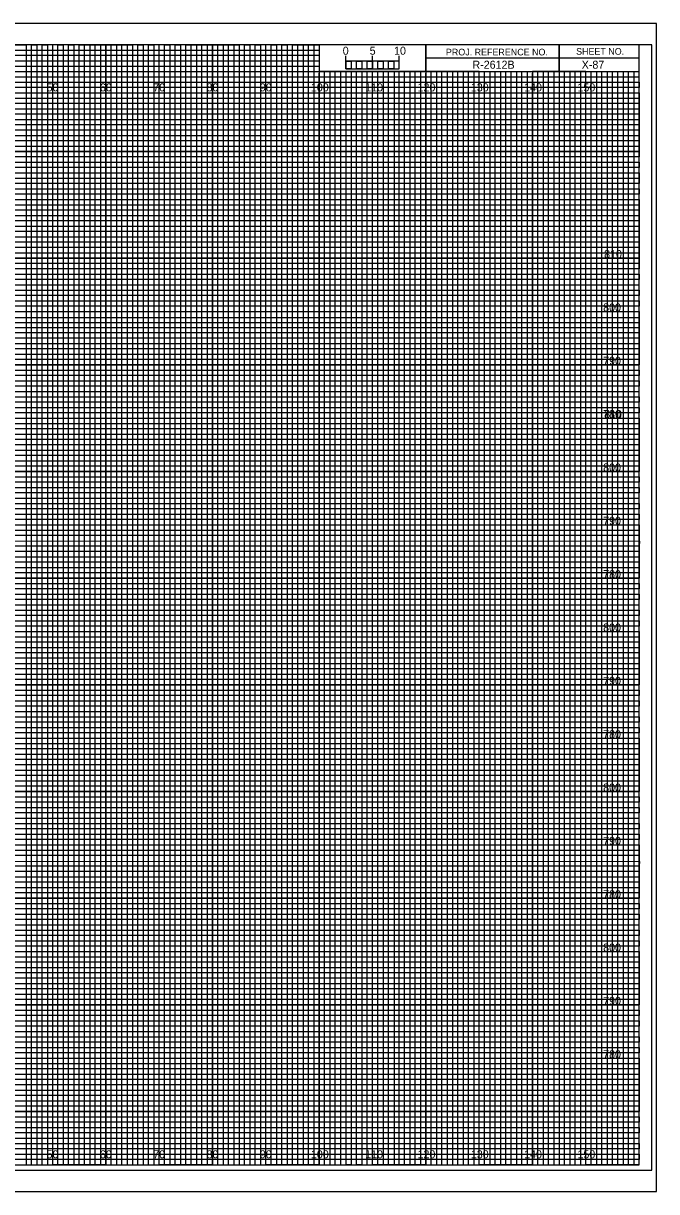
# Model space of a CAD drawing. Extents: x -13 to 323, y -5 to 214.
# Drawn here: x 204.5 to 323.3, y -5 to 214 of the extents above; entities that cross this region are included whole.
import ezdxf

# ---------------------------------------------------------------- set-up
doc = ezdxf.new("R2010")
doc.units = 0
for name, color, linetype in [('Prop XS Bar Scale Labels', 7, 'Continuous'), ('Prop XS Elevation Labels', 7, 'Continuous'), ('Prop XS Offset Labels', 7, 'Continuous'), ('Prop XS Project Number', 7, 'Continuous'), ('Prop XS Sheet Number', 7, 'Continuous'), ('Sheet Cross Section CELL', 7, 'Continuous'), ('Sheet Cross Section Grid Major CELL', 7, 'Continuous'), ('Sheet Cross Section Grid Middle CELL', 7, 'Continuous'), ('Sheet Cross Section Grid Minor 1 CELL', 7, 'Continuous'), ('Sheet Cross Section Grid Minor 2 CELL', 7, 'Continuous'), ('Sheet Cross Section Scale CELL', 7, 'Continuous'), ('Sheet Cutting Line CELL', 7, 'Continuous'), ('Sheet DOT Grid CELL', 7, 'Continuous'), ('Sheet Plot Border Inside CELL', 7, 'Continuous'), ('Sheet Plot Border Outside CELL', 7, 'Continuous')]:
    doc.layers.add(name, color=color, linetype=linetype)

msp = doc.modelspace()

# ---------------------------------------------------------------- linework, layer by layer
at = {"layer": 'Sheet Cross Section CELL'}
for p, q in [((305, 210), (305, 205)), ((305, 205), (305, 210)), ((280, 207.5), (280, 205)), ((320, 207.49), (280, 207.49)), ((280, 205), (320, 205))]:
    msp.add_line(p, q, dxfattribs=at)
for points in [[(320, 210), (0, 210), (0, 0), (320, 0)], [(280, 210), (260, 210), (260, 205.03), (280, 205.03)], [(320, 210), (280, 210), (280, 205), (320, 205)]]:
    msp.add_lwpolyline(points, close=True, dxfattribs=at)
at = {"layer": 'Sheet Cross Section Grid Major CELL'}
for p, q in [((210, 210), (200, 210)), ((210, 0), (210, 210)), ((230, 210), (220, 210)), ((220, 210), (220, 0)), ((230, 0), (230, 210)), ((250, 210), (240, 210)), ((240, 210), (240, 0)), ((250, 0), (250, 210)), ((260, 210), (260, 0)), ((270, 0), (270, 205)), ((290, 205), (280, 205)), ((280, 205), (280, 0)), ((290, 0), (290, 205)), ((310, 205), (300, 205)), ((300, 205), (300, 0)), ((310, 0), (310, 205)), ((220, 0), (210, 0)), ((240, 0), (230, 0)), ((260, 0), (250, 0)), ((280, 0), (270, 0)), ((300, 0), (290, 0)), ((320, 0), (310, 0)), ((320, 0), (320, 0))]:
    msp.add_line(p, q, dxfattribs=at)
for points in [[(0, 200), (320, 200), (320, 190), (0, 190)], [(0, 180), (320, 180), (320, 170), (0, 170)], [(0, 160), (320, 160), (320, 150), (0, 150)], [(0, 140), (320, 140), (320, 130), (0, 130)], [(0, 120), (320, 120), (320, 110), (0, 110)], [(0, 100), (320, 100), (320, 90), (0, 90)], [(0, 80), (320, 80), (320, 70), (0, 70)], [(0, 60), (320, 60), (320, 50), (0, 50)], [(0, 40), (320, 40), (320, 30), (0, 30)], [(0, 20), (320, 20), (320, 10), (0, 10)]]:
    msp.add_lwpolyline(points, dxfattribs=at)
at = {"layer": 'Sheet Cross Section Grid Middle CELL'}
for points in [[(195, 210), (205, 210), (205, 0), (215, 0), (215, 210), (225, 210), (225, 0), (235, 0), (235, 210), (245, 210), (245, 0), (255, 0), (255, 210), (259.93, 210), (260, 210), (260, 205), (264.99, 205), (264.99, 0), (275, 0), (275, 205), (285, 205), (285, 0), (295, 0), (295, 205), (305, 205), (305, 0), (315, 0), (315, 205)], [(0, 205), (275, 205)], [(0, 185), (320, 185), (320, 195), (0, 195)], [(0, 165), (320, 165), (320, 175), (0, 175)], [(0, 145), (320, 145), (320, 155), (0, 155)], [(0, 125), (320, 125), (320, 135), (0, 135)], [(0, 105), (320, 105), (320, 115), (0, 115)], [(0, 85), (320, 85), (320, 95), (0, 95)], [(0, 65), (320, 65), (320, 75), (0, 75)], [(0, 45), (320, 45), (320, 55), (0, 55)], [(0, 25), (320, 25), (320, 35), (0, 35)], [(0, 5), (320, 5), (320, 15), (0, 15)]]:
    msp.add_lwpolyline(points, dxfattribs=at)
at = {"layer": 'Sheet Cross Section Grid Minor 1 CELL'}
for p, q in [((0, 209), (260, 209)), ((260, 209), (260, 207.98)), ((260, 207.98), (0, 207.98)), ((0, 207), (260, 207)), ((260, 205.89), (0, 205.89)), ((260, 207), (260, 205.89)), ((0, 204), (320, 204))]:
    msp.add_line(p, q, dxfattribs=at)
for points in [[(0, 203), (270, 203), (320, 203), (320, 202), (0, 202)], [(0, 201), (320, 201), (320, 199), (0, 199)], [(0, 198), (320, 198), (320, 197), (0, 196.98)], [(0, 196), (320, 196), (320, 194), (0, 194)], [(0, 193), (320, 193), (320, 192), (0, 192)], [(0, 191), (320, 191), (320, 189), (0, 189)], [(0, 188), (320, 188), (320, 187), (0, 187)], [(0, 186), (320, 186), (320, 184), (0, 184)], [(0, 183), (320, 183), (320, 182), (0, 182)], [(0, 181), (320, 181), (320, 179), (0, 179)], [(0, 178), (320, 178), (320, 177), (0, 177)], [(0, 176), (320, 176), (320, 173.95), (320, 173), (320, 172), (0, 172)], [(0, 174), (320, 174), (320, 173), (0, 173)], [(0, 171), (320, 171), (320, 169), (0, 169.03)], [(0, 169.03), (320, 169), (320, 168), (0, 168)], [(0, 167), (320, 167), (320, 166), (0, 166)], [(0, 164), (320, 164), (320, 163), (0, 163)], [(0, 162), (320, 162), (320, 161), (0, 161)], [(-0.07, 158.89), (320, 158.89), (320, 157.88), (-0.07, 157.88)], [(0, 157), (320, 157), (320, 156), (0, 156)], [(0, 154), (320, 154), (320, 153), (0, 153)], [(0, 152), (320, 152), (320, 151), (0, 151)], [(0, 149), (320, 149), (320, 148), (0, 148)], [(0, 147), (320, 147), (320, 146), (0, 146)], [(0, 144), (320, 144), (320, 143), (0, 143)], [(0, 142), (320, 142), (320, 141), (0, 141)], [(0, 139), (320, 139), (319.99, 137.98), (0, 138)], [(0, 137), (320, 137), (320, 136), (0, 136)], [(0, 134), (320, 134), (320, 133), (0, 133)], [(0, 132), (320, 132), (320, 131), (0, 131)], [(0, 129), (320, 129), (320, 128), (0, 128)], [(0, 127), (320, 127), (320, 126), (0, 126)], [(0, 124), (320, 124), (320, 123), (0, 123)], [(0, 122), (320, 122), (320, 121), (0, 121)], [(0, 119), (320, 119), (320, 118), (0, 118)], [(0, 116.99), (320.07, 116.91), (320, 116), (0, 116)], [(0, 114), (320, 114), (320, 113), (0, 113)], [(0, 112), (320, 112), (320, 111), (0, 111)], [(0, 109), (320, 109), (320, 108), (0, 108)], [(0, 107), (320, 107), (320, 106), (0, 106)], [(0, 104), (320, 104), (320, 103), (0, 103)], [(0, 102), (320, 102), (320, 101), (0, 101)], [(0, 99), (320, 99), (320, 98), (0, 98)], [(0, 97), (320, 97), (320, 96), (0, 96)], [(0, 94), (320, 94), (320, 93), (0, 93)], [(0, 92), (320, 92), (320, 91), (0, 91)], [(0, 89), (320, 89), (320, 88), (0, 88)], [(0, 87), (320, 87), (320, 86), (0, 86)], [(0, 84), (320, 84), (320, 83), (0, 83)], [(0, 82), (320, 82), (320, 81), (0, 81)], [(0, 79), (320, 79), (319.99, 77.98), (0, 78)], [(0, 77), (320, 77), (320, 76), (0, 76)], [(0, 74), (320, 74), (320, 73), (0, 73)], [(0, 72), (320, 72), (320, 71), (0, 71)], [(0, 69), (320, 69), (320, 68), (0, 68)], [(0, 67), (320, 67), (320, 66), (0, 66)], [(0, 64), (320, 64), (320, 63), (0, 63)], [(0, 62), (320, 62), (320, 61), (0, 61)], [(0, 59), (320, 59), (320, 58), (0, 58)], [(0, 56.99), (320.07, 56.91), (320, 56), (0, 56)], [(0, 54), (320, 54), (320, 53), (0, 53)], [(0, 52), (320, 52), (320, 51), (0, 51)], [(0, 49), (320, 49), (320, 48), (0, 48)], [(0, 47), (320, 47), (320, 46), (0, 46)], [(0, 44), (320, 44), (320, 43), (0, 43)], [(0, 42), (320, 42), (320, 41), (0, 41)], [(0, 39), (320, 39), (320, 38), (0, 38)], [(0, 37), (320, 37), (320, 36), (0, 36)], [(0, 34), (320, 34), (320, 33), (0, 33)], [(0, 32), (320, 32), (320, 31), (0, 31)], [(0, 29), (320, 29), (320, 28), (0, 28)], [(0, 27), (320, 27), (320, 26), (0, 26)], [(0, 24), (320, 24), (320, 23), (0, 23)], [(0, 22), (320, 22), (320, 21), (0, 21)], [(0, 19), (320, 19), (320, 18), (0, 18)], [(0, 17), (320, 17), (320, 16), (0, 16)], [(0, 14), (320, 14), (320, 13), (0, 13)], [(0, 12), (320, 12), (320, 11), (0, 11)], [(0, 9), (320, 9), (320, 8), (0, 8)], [(0, 7), (320, 7), (320, 6), (0, 6)], [(0, 4), (320, 4), (320, 3), (0, 3)], [(0, 2), (320, 2), (320, 1), (0, 1)]]:
    msp.add_lwpolyline(points, dxfattribs=at)
at = {"layer": 'Sheet Cross Section Grid Minor 2 CELL'}
for p, q in [((267, 205), (266.01, 205)), ((266.01, 205), (266.01, 0)), ((267, 0), (267, 205)), ((269, 205), (268, 205)), ((268, 205), (268, 0)), ((269, 0), (269, 205)), ((266.01, 0), (265, 0)), ((268, 0), (267, 0))]:
    msp.add_line(p, q, dxfattribs=at)
for points in [[(205, 0), (206, 0), (206, 210), (207, 210), (207, 0)], [(207, 0), (208, 0), (208, 210), (209, 210), (209, 0)], [(210, 0), (211, 0), (211, 210), (212, 210), (212, 0)], [(212, 0), (213, 0), (213, 210), (214, 210), (214, 0)], [(215, 0), (216, 0), (216, 210), (217, 210), (217, 0)], [(217, 0), (218, 0), (218, 210), (219, 210), (219, 0)], [(220, 0), (221, 0), (221, 210), (222, 210), (222, 0)], [(222, 0), (223, 0), (223, 210), (224, 210), (224, 0)], [(225, 0), (226, 0), (226, 210), (227, 210), (227, 0)], [(227, 0), (228, 0), (228, 210), (229, 210), (229, 0)], [(230, 0), (231, 0), (231, 210), (232, 210), (232, 0)], [(232, 0), (233, 0), (233, 210), (234, 210), (234, 0)], [(235, 0), (236, 0), (236, 210), (237, 210), (237, 0)], [(237, 0), (238, 0), (238, 210), (239, 210), (239, 0)], [(240, 0), (241, 0), (241, 210), (242, 210), (242, 0)], [(242, 0), (243, 0), (243, 210), (244, 210), (244, 0)], [(245, 0), (246, 0), (246, 210), (247, 210), (247, 0)], [(247, 0), (248, 0), (248, 210), (249, 210), (249, 0)], [(250, 0), (251, 0), (251, 210), (252, 210), (252, 0)], [(252, 0), (253, 0), (253, 210), (254, 210), (254, 0)], [(255, 0), (256, 0), (256, 210), (257, 210), (257, 0)], [(257, 0), (258, 0), (258, 210), (259, 210), (259, 0)], [(260, 0), (261, 0), (261, 205), (262.02, 205), (262.02, 0)], [(262, 0), (263, 0), (263, 205), (263.99, 205), (263.99, 0)], [(270, 0), (270.98, 0), (270.98, 205), (272, 205), (272, 0)], [(272, 0), (273, 0), (273, 205), (274.05, 205), (274.05, 0)], [(275, 0), (276, 0), (276, 205), (277, 205), (277, 0)], [(277, 0), (278, 0), (278, 205), (279, 205), (279, 0)], [(280, 0), (281, 0), (281, 205), (282, 205), (282, 0)], [(282, 0), (283, 0), (283, 205), (284, 205), (284, 0)], [(285, 0), (286, 0), (286, 205), (287, 205), (287, 0)], [(287, 0), (288, 0), (288, 205), (289, 205), (289, 0)], [(290, 0), (291, 0), (291, 205), (292, 205), (292, 0)], [(292, 0), (293, 0), (293, 205), (294, 205), (294, 0)], [(295, 0), (296, 0), (296, 205), (297, 205), (297, 0)], [(297, 0), (298, 0), (298, 205), (299, 205), (299, 0)], [(300, 0), (301, 0), (301, 205), (302, 205), (302, 0)], [(302, 0), (303, 0), (303, 205), (304, 205), (304, 0)], [(305, 0), (306, 0), (306, 205), (307, 205), (307, 0)], [(307, 0), (308, 0), (308, 205), (309, 205), (309, 0)], [(310, 0), (311, 0), (311, 205), (312, 205), (312, 0)], [(312, 0), (313, 0), (313, 205), (314, 205), (314, 0)], [(315, 0), (316, 0), (316, 205), (317, 205), (317, 0)], [(317, 0), (318, 0), (318, 205), (319, 205), (319, 0)]]:
    msp.add_lwpolyline(points, dxfattribs=at)
at = {"layer": 'Sheet Cross Section Scale CELL'}
for p, q in [((265, 205.49), (265, 207.9)), ((265, 206.9), (265, 207.9)), ((270, 205.49), (270, 207.9)), ((275, 205.49), (275, 207.9)), ((275, 206.9), (275, 207.9))]:
    msp.add_line(p, q, dxfattribs=at)
for points in [[(275, 206.9), (265, 206.9), (265, 205.49), (275, 205.49)], [(265, 206.9), (266, 206.9), (266, 205.49), (265, 205.49)], [(267, 206.9), (268, 206.9), (268, 205.49), (267, 205.49)], [(269, 206.9), (270, 206.9), (270, 205.49), (269, 205.49)], [(271, 206.9), (272, 206.9), (272, 205.49), (271, 205.49)], [(273, 206.9), (274, 206.9), (274, 205.49), (273, 205.49)]]:
    msp.add_lwpolyline(points, close=True, dxfattribs=at)
at = {"layer": 'Sheet Cutting Line CELL'}
for p, q in [((323.3, 214), (-13.4, 214)), ((-13.4, -5), (323.3, -5))]:
    msp.add_line(p, q, dxfattribs=at)
at = {"layer": 'Sheet DOT Grid CELL'}
for p, q in [((210, 0), (210, 210)), ((220, 0), (220, 210)), ((230, 0), (230, 210)), ((240, 0), (240, 210)), ((250, 0), (250, 210)), ((260, 0), (260, 204.69)), ((270, 0), (270, 204.69)), ((280, 0), (280, 204.69)), ((290, 0), (290, 204.69)), ((300, 0), (300, 204.69)), ((310, 0), (310, 204.69)), ((0, 200), (320, 200)), ((0, 190), (320, 190)), ((0, 180), (320, 180)), ((0, 170), (320, 170)), ((0, 160), (320, 160)), ((0, 150), (320, 150)), ((0, 140), (320, 140)), ((0, 130), (320, 130)), ((0, 120), (320, 120)), ((0, 110), (320, 110)), ((0, 100), (320, 100)), ((0, 90), (320, 90)), ((0, 80), (320, 80)), ((0, 70), (320, 70)), ((0, 60), (320, 60)), ((0, 50), (320, 50)), ((0, 40), (320, 40)), ((0, 30), (320, 30)), ((0, 20), (320, 20)), ((0, 10), (320, 10))]:
    msp.add_line(p, q, dxfattribs=at)
at = {"layer": 'Sheet Plot Border Inside CELL'}
msp.add_lwpolyline([(-10.8, -1), (322.4, -1), (322.4, 210), (-10.8, 210)], close=True, dxfattribs=at)
at = {"layer": 'Sheet Plot Border Outside CELL'}
msp.add_lwpolyline([(-13.4, -5), (323.3, -5), (323.3, 214), (-13.4, 214)], close=True, dxfattribs=at)

# ---------------------------------------------------------------- texts
at = {"layer": 'Prop XS Bar Scale Labels'}
for s, p in [('5', (269.47, 208.12)), ('10', (274.04, 208.12))]:
    msp.add_text(s, height=1.5, dxfattribs=at).set_placement(p)
at = {"layer": 'Prop XS Elevation Labels'}
for s, p in [('810', (313.44, 170)), ('800', (313.26, 160)), ('790', (313.26, 150)), ('780', (313.26, 140)), ('810', (313.44, 140)), ('800', (313.26, 130)), ('790', (313.26, 120)), ('780', (313.26, 110)), ('800', (313.26, 100)), ('790', (313.26, 90)), ('780', (313.26, 80)), ('800', (313.26, 70)), ('790', (313.26, 60)), ('780', (313.26, 50)), ('800', (313.26, 40)), ('790', (313.26, 30)), ('780', (313.26, 20))]:
    msp.add_text(s, height=1.5, dxfattribs=at).set_placement(p)
at = {"layer": 'Prop XS Offset Labels'}
for s, p in [('50', (208.86, 201.25)), ('60', (218.86, 201.25)), ('70', (228.86, 201.25)), ('80', (238.86, 201.25)), ('90', (248.86, 201.25)), ('100', (258.44, 201.25)), ('110', (268.62, 201.25)), ('120', (278.44, 201.25)), ('130', (288.44, 201.25)), ('140', (298.44, 201.25)), ('150', (308.44, 201.25)), ('50', (208.86, 1.25)), ('60', (218.86, 1.25)), ('70', (228.86, 1.25)), ('80', (238.86, 1.25)), ('90', (248.86, 1.25)), ('100', (258.44, 1.25)), ('110', (268.62, 1.25)), ('120', (278.44, 1.25)), ('130', (288.44, 1.25)), ('140', (298.44, 1.25)), ('150', (308.44, 1.25))]:
    msp.add_text(s, height=1.5, dxfattribs=at).set_placement(p)
at = {"layer": 'Prop XS Project Number'}
msp.add_text('R-2612B', height=1.5, dxfattribs=at).set_placement((288.74, 205.5))
at = {"layer": 'Prop XS Sheet Number'}
msp.add_text('X-87', height=1.5, dxfattribs=at).set_placement((309.24, 205.5))
at = {"layer": 'Sheet Cross Section CELL'}
for s, p in [('PROJ. REFERENCE NO.', (283.77, 207.99)), ('SHEET NO.', (308.19, 208.12))]:
    msp.add_text(s, height=1.25, dxfattribs=at).set_placement(p)
at = {"layer": 'Sheet Cross Section Scale CELL'}
msp.add_text('0', height=1.5, dxfattribs=at).set_placement((264.41, 208.12))

doc.saveas('drawing.dxf')
